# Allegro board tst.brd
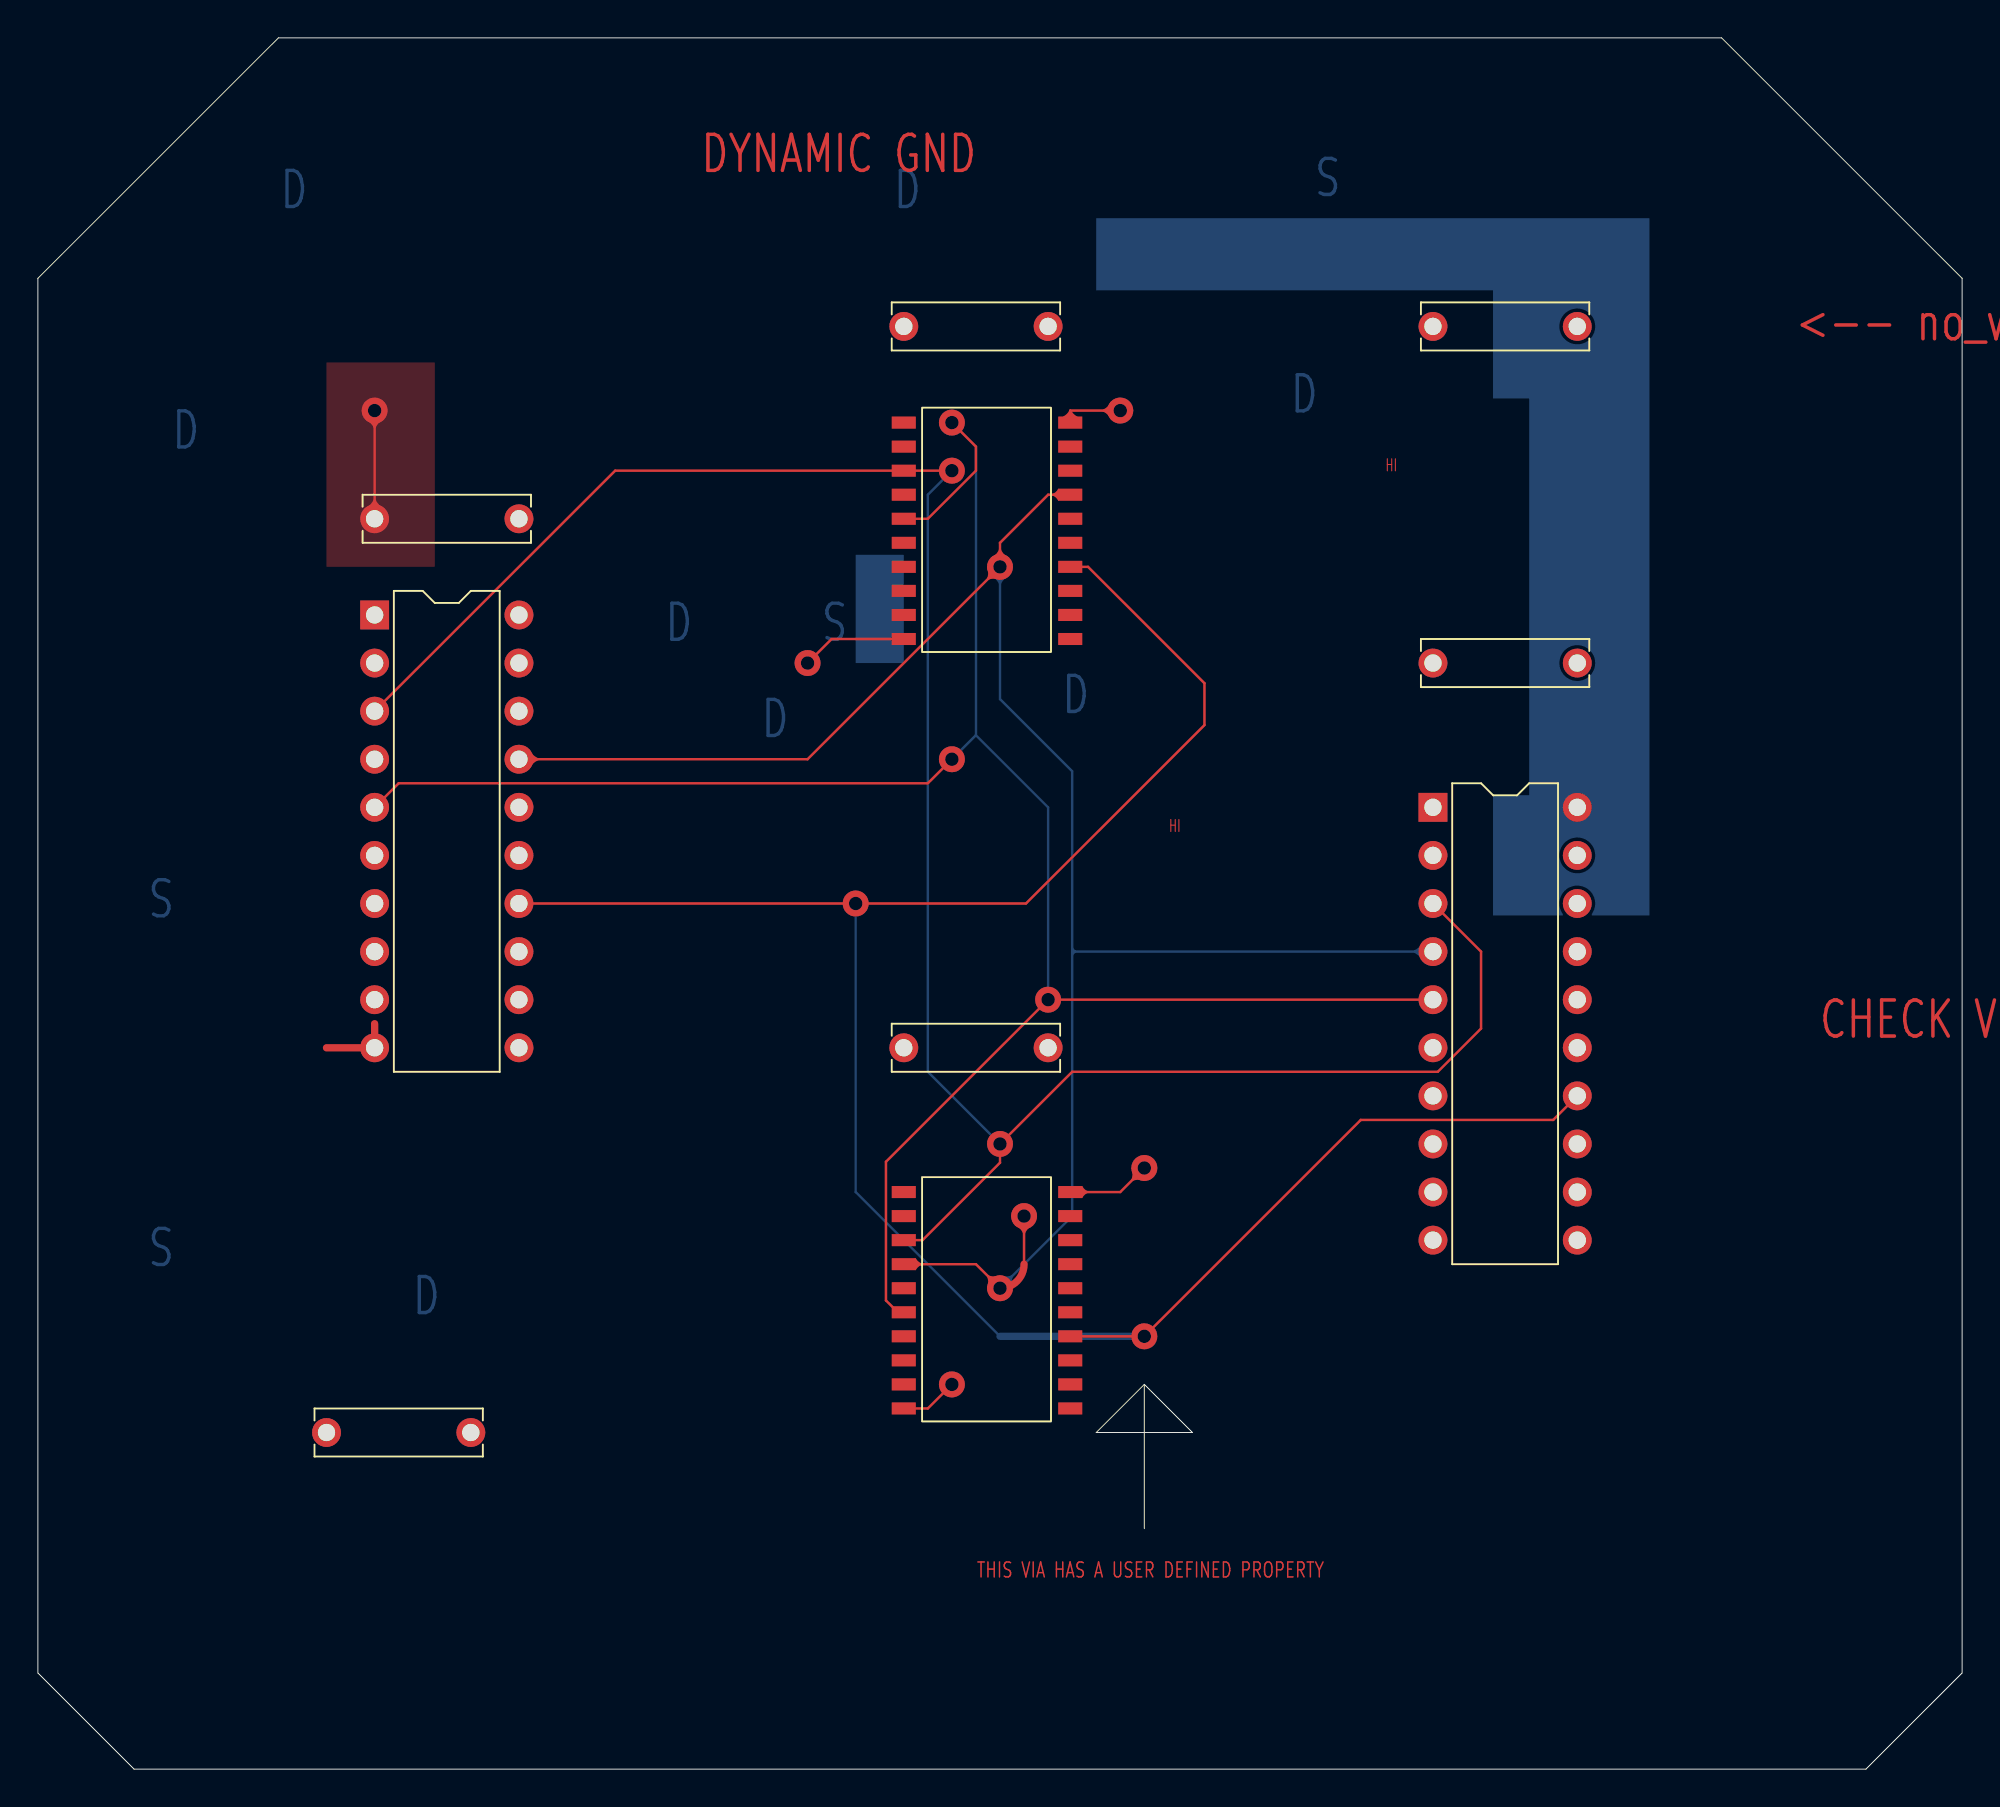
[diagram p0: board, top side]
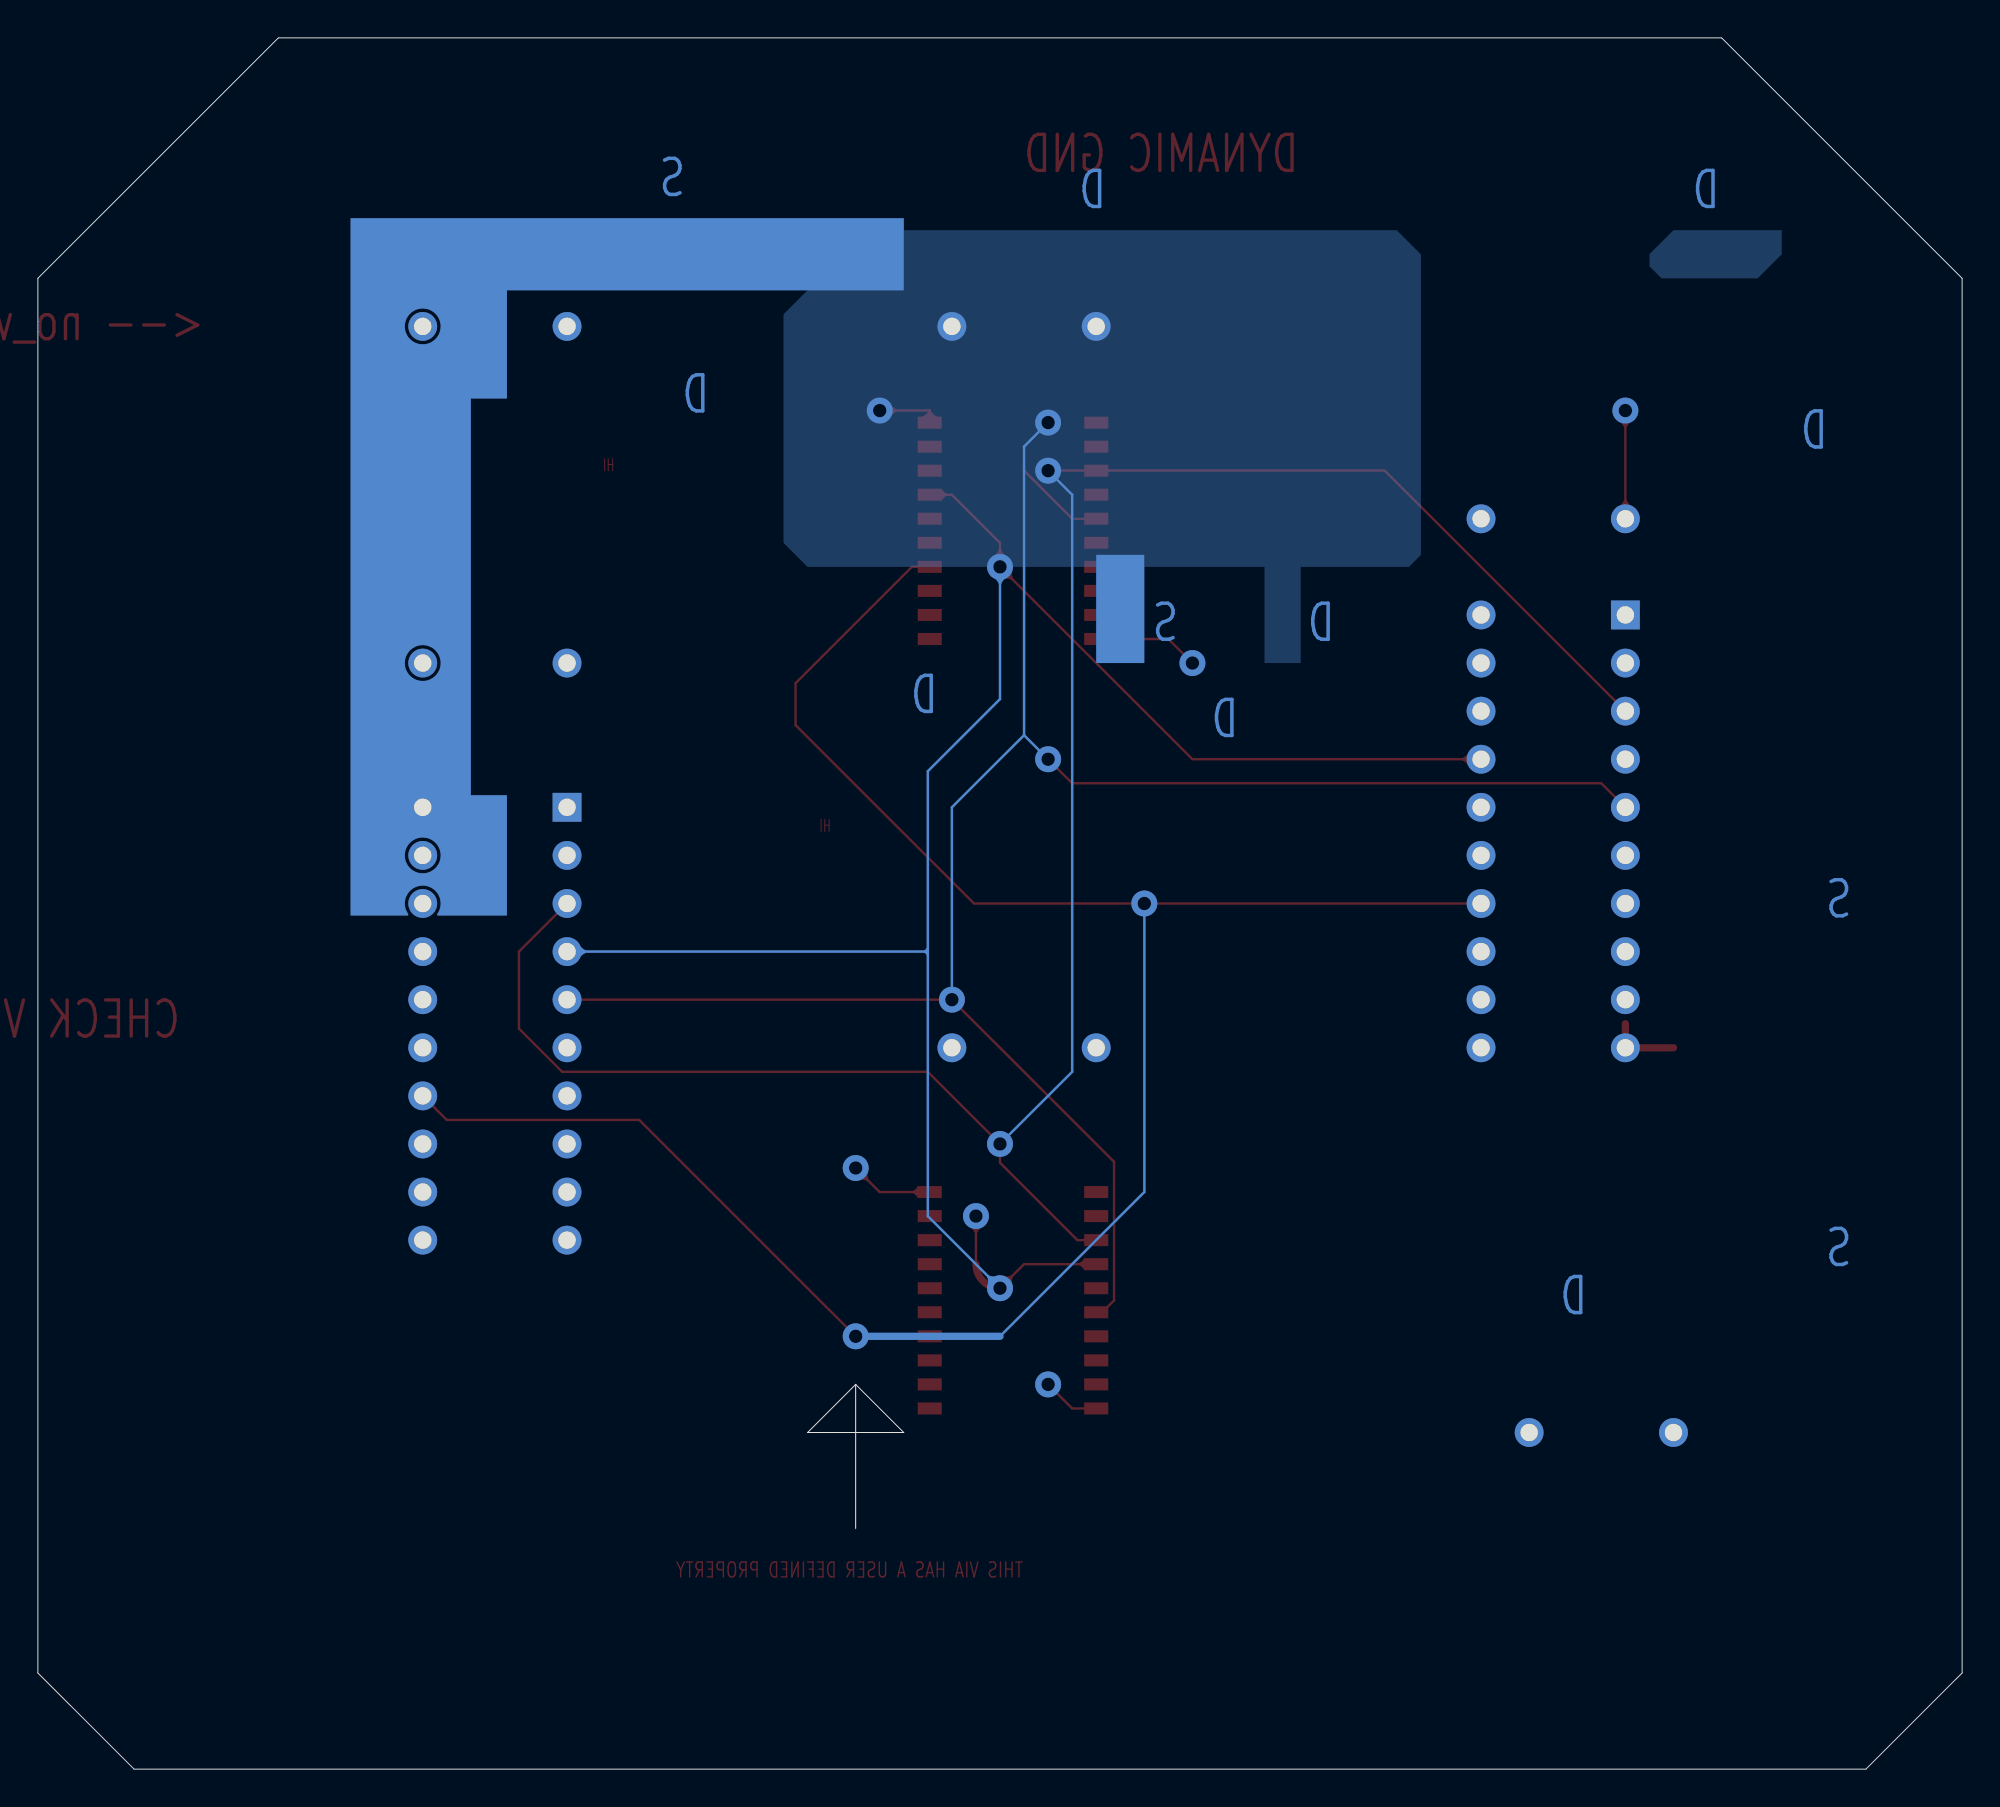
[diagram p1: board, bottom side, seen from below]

Outline 101.6 x 91.44 mm; copper layers: TOP, GND, SIG2, SIG3, POWER, BOTTOM. Coordinates in mm from the lower left corner of the outline.
Outline path: 58.42,20.32 55.88,17.78 60.96,17.78 58.42,20.32 ; 58.42,20.32 58.42,12.7 ; 0,78.74 0,5.08 5.08,0 96.52,0 101.6,5.08 101.6,78.74 88.9,91.44 12.7,91.44 0,78.74

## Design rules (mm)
constraint set DEFAULT: min track width 0.025
net group CLS3: nets VCC
net group CLS4: nets A C Q2
net group MG1: nets JUNK

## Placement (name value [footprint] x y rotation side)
C1  VAL  [CAP300]  45.72 76.2 0 top
C2  VAL  [CAP300]  17.78 66.04 0 top
C3  VAL  [CAP300]  45.72 38.1 0 top
C4  VAL  [CAP300]  73.66 58.42 0 top
C5  VAL  [CAP300]  73.66 76.2 0 top
C6  VAL  [CAP300]  15.24 17.78 0 top
U1  ***  [DIP20_3]  17.78 60.96 0 top
U2  ***  [DIP20_3]  73.66 50.8 0 top
U3  ***  [SOIC20]  45.72 71.12 0 top
U4  ***  [SOIC20]  45.72 30.48 0 top

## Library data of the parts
C1-C6 = FCAP-1: User Part Number: ***; Tolerance: ***; alternate symbols: (CAP400)
U1-U4 = 74HC541-1

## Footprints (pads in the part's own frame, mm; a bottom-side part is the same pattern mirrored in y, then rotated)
CAP300
  round 1.524 hole 0.914: 1(0,0) 2(7.62,0)
DIP20_3
  rect 1.524x1.524 hole 0.914: 1(0,0)
  round 1.524 hole 0.914: 2(0,-2.54) 3(0,-5.08) 4(0,-7.62) 5(0,-10.16) 6(0,-12.7) 7(0,-15.24) 8(0,-17.78) 9(0,-20.32) 10(0,-22.86) 11(7.62,-22.86) 12(7.62,-20.32) 13(7.62,-17.78) 14(7.62,-15.24) 15(7.62,-12.7) 16(7.62,-10.16) 17(7.62,-7.62) 18(7.62,-5.08) 19(7.62,-2.54) 20(7.62,0)
SOIC20
  rect 1.27x0.635 smd: 1(0,0) 2(0,-1.27) 3(0,-2.54) 4(0,-3.81) 5(0,-5.08) 6(0,-6.35) 7(0,-7.62) 8(0,-8.89) 9(0,-10.16) 10(0,-11.43) 11(8.788,-11.43) 12(8.788,-10.16) 13(8.788,-8.89) 14(8.788,-7.62) 15(8.788,-6.35) 16(8.788,-5.08) 17(8.788,-3.81) 18(8.788,-2.54) 19(8.788,-1.27) 20(8.788,0)

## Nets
GND: C1.2(GROUND<0>) C2.2(GROUND<0>) C3.2(GROUND<0>) C4.2(GROUND<0>) U1.10 U1.19(-OE2) U2.10 U2.19(-OE2) U3.10 U4.10
VCC: C1.1(POWER<0>) C2.1(POWER<0>) C3.1(POWER<0>) C4.1(POWER<0>) U1.20 U2.20 U3.20 U4.20
A: U1.14(Y<0>) U2.14(Y<0>) U3.14(Y<0>) U4.14(Y<0>)
C: U1.17(Y<0>) U2.4(A<0>) U3.17(Y<0>) U4.4(A<0>)
JUNK: U1.3(A<0>) U2.3(A<0>) U3.3(A<0>) U4.3(A<0>)
Q2: U1.5(A<0>) U2.5(A<0>) U3.5(A<0>) U4.6(A<0>)

Pads without a net: C5 1 2; C6 1 2; U1 1 2 4 6 7 8 9 11 12 13 15 16 18; U2 1 2 6 7 8 9 11 12 13 15 16 17 18; U3 1 2 4 6 7 8 9 11 12 13 15 16 18 19; U4 1 2 5 7 8 9 11 12 13 15 16 17 18 19

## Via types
v1: diameter 1.372, hole 0.711, TOP to BOTTOM, 15 vias

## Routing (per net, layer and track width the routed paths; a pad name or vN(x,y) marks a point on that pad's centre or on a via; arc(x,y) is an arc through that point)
GND: length 20.1
  TOP w0.127: v1(48.26,20.32) 46.99,19.05 U4.10 ; U3.10 41.91,59.69 v1(40.64,58.42)
  TOP w0.381: 15.24,38.1 U1.10 17.78,39.37
  GND w0.127: C1.2 53.97,76.2 ; C1.2 53.34,73.66 ; C1.2 50.16,76.2 ; C1.2 53.34,77.47
VCC: length 13.4
  TOP w0.127: v1(58.42,31.75) 57.15,30.48 U4.20 ; U3.20 54.51,71.74 54.52,71.75 v1(57.15,71.75) ; C2.1 v1(17.78,71.75)
A: length 117.6
  TOP w0.127: U2.14 80.01,34.29 69.85,34.29 v1(58.42,22.86) U4.14 ; U3.14 55.45,63.5 61.59,57.35 61.59,55.14 52.17,45.72 v1(43.18,45.72) U1.14
  BOTTOM w0.127: 50.8,22.86 43.18,30.48 v1(43.18,45.72)
  BOTTOM w0.381: v1(58.42,22.86) 50.8,22.86
C: length 106.1
  TOP w0.127: 52.07,26.67 v1(52.07,29.21) ; U1.17 40.64,53.34 v1(50.8,63.5) 50.8,64.77 53.34,67.31 U3.17 ; v1(50.8,25.4) 49.53,26.67 U4.4
  TOP w0.381: v1(50.8,25.4) arc(51.7,25.77) 52.07,26.67
  BOTTOM w0.127: v1(50.8,63.5) 50.8,56.51 54.61,52.71 54.61,43.18 ; v1(50.8,25.4) 54.61,29.21 54.61,43.18 ; 54.61,43.18 U2.4
JUNK: length 116.8
  TOP w0.127: U1.3 30.48,68.58 U3.3 v1(48.26,68.58) ; U2.3 76.2,43.18 76.2,39.12 73.91,36.83 54.61,36.83 v1(50.8,33.02) 50.8,32.03 46.71,27.94 U4.3
  BOTTOM w0.127: v1(48.26,68.58) 46.99,67.31 46.99,36.83 v1(50.8,33.02)
Q2: length 114.8
  TOP w0.127: U2.5 v1(53.34,40.64) 44.78,32.08 44.78,24.75 45.4,24.13 U4.6 ; v1(48.26,71.12) 49.53,69.85 49.53,68.58 46.99,66.04 U3.5 ; U1.5 19.05,52.07 46.99,52.07 v1(48.26,53.34)
  BOTTOM w0.127: 49.53,54.61 v1(48.26,53.34) ; 49.53,54.61 49.53,69.85 v1(48.26,71.12) ; 49.53,54.61 53.34,50.8 v1(53.34,40.64)

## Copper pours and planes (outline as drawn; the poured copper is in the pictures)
GND on GND (solid shape): 99.69,43.82 87.63,43.82 87.63,48.9 96.52,48.9 96.52,51.43 94.61,51.43 94.61,48.9 87.63,48.9 87.63,55.24 90.17,55.24 90.17,62.87 99.69,62.87
GND on GND (solid shape): outline of 210 points within 20.32,6.98 66.67,27.3
GND on GND (solid shape): outline of 501 points within 21.59,32.45 94.55,79.95
GND on POWER (solid shape): 50.16,22.23 50.16,15.88 49.53,15.24 41.27,15.24 38.73,17.78 38.73,20.95 40.64,22.86 49.53,22.86
GND on GND: 60.96,27.94 71.75,27.94 71.75,24.13 86.36,24.13 86.36,54.61 69.85,54.61 69.85,38.73 60.96,38.73
GND on GND: 52.07,38.73 60.96,36.2
GND on SIG2: 69.22,73.03 87.63,73.03 87.63,24.13 44.45,24.13 44.45,66.04 69.22,66.04
GND on SIG2: 13.97,80.01 46.99,80.01 46.99,29.21 10.79,29.21 10.79,73.03 13.97,73.03
GND on SIG3: 76.83,30.48 83.82,30.48 84.45,29.84 84.45,19.05 74.93,19.05 74.3,19.69 74.3,27.94
GND on SIG3: 69.22,36.2 77.47,36.2 78.11,35.56 78.11,24.13 75.56,21.59 70.48,21.59 68.58,23.49 68.58,35.56
GND on POWER: 7.62,46.99 33.66,46.99 33.66,62.87 41.91,62.87 42.55,62.23 42.55,56.51 36.2,56.51 35.56,55.88 35.56,27.31 35.57,27.3 47.62,27.3 53.34,21.59 53.34,15.88 51.44,13.97 12.06,13.97 7.62,18.41
GND on POWER: 8.89,45.09 29.21,45.09 29.21,29.84 13.33,29.84 8.89,35.56
VCC on BOTTOM (solid shape): outline of 277 points within 55.88,45.09 85.09,81.91
VCC on POWER (solid shape): 66.67,64.13 55.25,64.13 55.25,73.66 66.67,73.66
VCC on POWER (solid shape): 77.47,55.24 66.67,55.24 66.67,73.66 77.47,73.66
VCC on POWER (solid shape): outline of 875 points within 12.06,49.48 50.23,81.28
VCC on BOTTOM: 29.84,81.28 57.78,81.28 62.23,76.84 62.23,64.77 60.96,63.5 29.21,63.5 28.57,64.13 28.57,80.01
VCC on BOTTOM: 9.52,81.28 15.24,81.28 16.51,80.01 16.51,79.38 15.88,78.74 10.79,78.74 9.52,80.01
VCC on SIG3: 43.81,73.66 53.34,73.66 55.88,71.12 55.88,68.58 62.23,68.58 62.23,81.91 61.59,82.55 44.45,82.55 43.18,81.28 45.09,79.38 45.72,79.38 45.72,74.29 43.81,74.29
VCC on SIG3: 12.7,78.74 50.8,78.74 54.61,74.93 54.61,36.83 53.34,35.56 11.43,35.56 11.43,77.47
VCC on SIG3: 41.91,41.27 61.59,41.27 61.59,26.03 45.09,26.03 41.91,29.21
VCC on SIG3: 80.01,54.61 52.7,54.61 52.07,55.24 52.07,61.6 53.34,62.87 80.01,62.87
VCC on POWER: 40,49.53 40,29.21 51.44,29.21 51.44,49.53
VCC on POWER: 55.25,27.94 65.41,27.94 65.41,45.72 51.44,45.72 51.44,33.66 55.25,33.66
Net_1 on TOP: 15.24,74.29 15.24,63.5 20.95,63.5 20.95,74.29
Net_2 on GND (solid shape): 20.95,32.38 13.33,32.38 13.33,59.69 15.88,59.69 15.88,36.83 19.69,36.83 19.69,62.23 15.88,62.23 15.88,59.69 13.33,59.69 13.33,64.77 19.69,64.77 19.69,67.31 15.88,67.31 15.88,64.77 13.33,64.77 13.33,72.39 15.88,72.39 15.88,71.12 17.14,71.12 17.14,69.85 18.41,69.85 18.41,71.12 19.69,71.12 19.69,72.39 18.41,72.39 18.41,73.66 17.14,73.66 17.14,72.39 13.33,72.39 13.33,73.66 14.6,74.93 20.95,74.93
Net_3 on BOTTOM (solid shape): 45.72,58.42 43.18,58.42 43.18,64.13 45.72,64.13
Net_4 on BOTTOM: 34.92,58.42 34.92,64.13 36.83,64.13 36.83,58.42

Small or netless copper shapes (teardrops, artwork), in the pictures only: 13 on TOP, 4 on BOTTOM

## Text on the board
BOTTOM: S | D | INCLUDE SHAPE ON POWER SUBCLASS | TRY MERGE ON ALL OF THESE AND
TOP: HI | THIS VIA HAS A USER DEFINED PROPERTY | DYNAMIC GND | <-- no_void prop on pin | CHECK VOID
GND: S | D
SIG2: TEXT_TEST | DYN OVERSIZE ON VIA | DYNAMIC HATCHES DIFFERENT WIDTHS | DYN OVERSIZE ON PIN
SIG3: 2 OVERLAPPING | DYNAMIC SHAPES | DYN | FIXED DYN SHAPE
POWER: D | S
